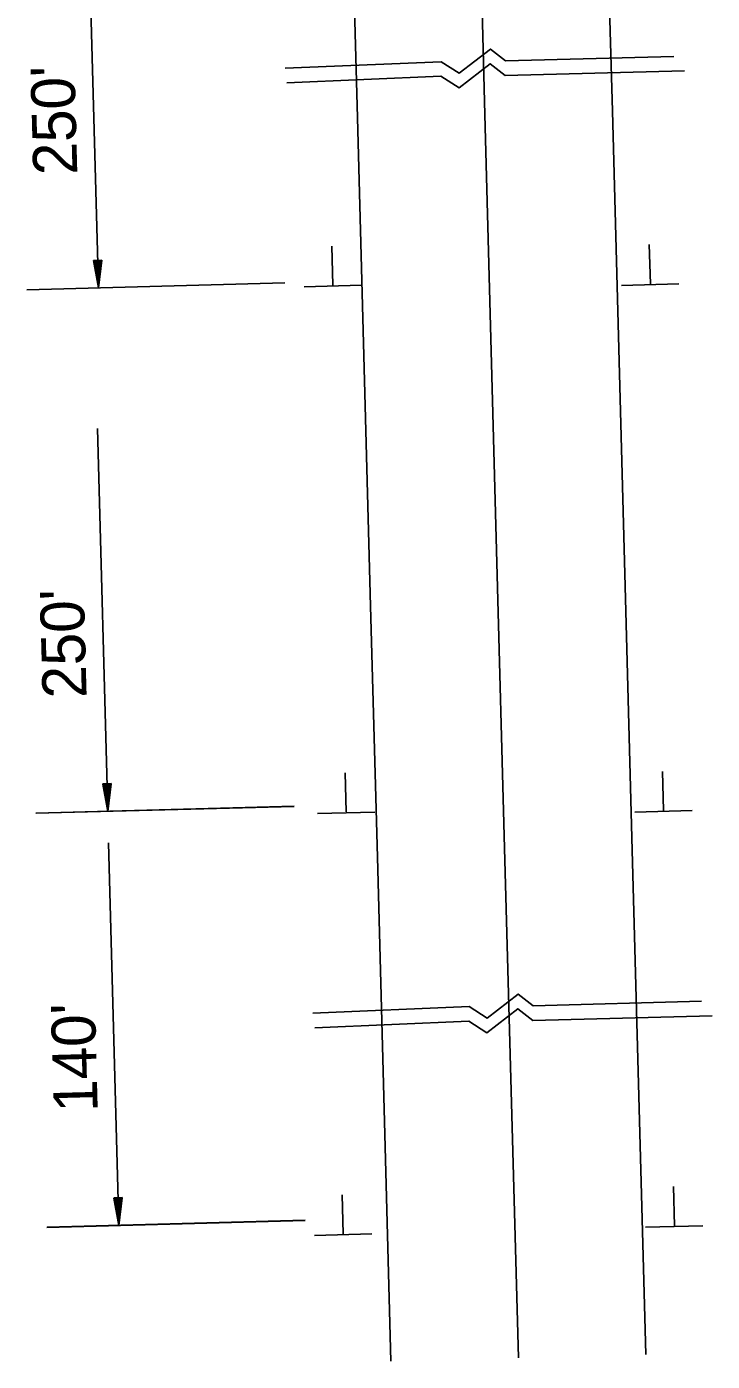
# Model space of a CAD drawing. Extents: x 1926836 to 1933254, y 596317 to 604524.
# Drawn here: x 1930895.5 to 1930991.2, y 598192.1 to 598378.3 of the extents above; entities that cross this region are included whole.
import ezdxf

# ---------------------------------------------------------------- set-up
doc = ezdxf.new("R2010")
doc.units = 0
doc.layers.add('Default', color=7, linetype='Continuous')

msp = doc.modelspace()

# ---------------------------------------------------------------- linework, layer by layer
at = {"layer": 'Default'}
for p, q in [((1930941.69, 598365.58), (1930939.79, 598436.16)), ((1930959.47, 598366.06), (1930957.58, 598436.64)), ((1930977.25, 598366.53), (1930975.36, 598437.12)), ((1930905.56, 598341.88), (1930904.12, 598395.26)), ((1930943.52, 598297.44), (1930941.69, 598365.58)), ((1930961.15, 598303.48), (1930959.47, 598366.06)), ((1930979.08, 598298.45), (1930977.25, 598366.53)), ((1930938.27, 598342.24), (1930938.12, 598347.7)), ((1930982.55, 598342.44), (1930982.4, 598347.9)), ((1930906.03, 598345.73), (1930904.88, 598345.7)), ((1930904.88, 598345.7), (1930905.56, 598341.88)), ((1930904.97, 598345.7), (1930905.54, 598342.52)), ((1930905.07, 598345.7), (1930905.52, 598343.18)), ((1930905.17, 598345.71), (1930905.51, 598343.82)), ((1930905.27, 598345.71), (1930905.49, 598344.47)), ((1930905.36, 598345.71), (1930905.47, 598345.11)), ((1930905.54, 598345.72), (1930905.47, 598345.11)), ((1930905.64, 598345.72), (1930905.49, 598344.47)), ((1930905.74, 598345.72), (1930905.51, 598343.82)), ((1930905.84, 598345.72), (1930905.52, 598343.18)), ((1930905.93, 598345.73), (1930905.54, 598342.52)), ((1930906.03, 598345.73), (1930905.56, 598341.88)), ((1930895.54, 598341.61), (1930931.56, 598342.58)), ((1930942.25, 598342.23), (1930934.25, 598342.02)), ((1930986.53, 598342.43), (1930978.53, 598342.21)), ((1930906.86, 598268.84), (1930905.42, 598322.22)), ((1930962.22, 598263.66), (1930961.15, 598303.48)), ((1930980.02, 598263.41), (1930979.08, 598298.45)), ((1930944.46, 598262.4), (1930943.52, 598297.44)), ((1930940.12, 598268.72), (1930939.98, 598274.18)), ((1930984.4, 598268.92), (1930984.25, 598274.38)), ((1930907.31, 598272.65), (1930906.16, 598272.62)), ((1930906.16, 598272.62), (1930906.84, 598268.8)), ((1930907.33, 598272.69), (1930906.18, 598272.66)), ((1930906.18, 598272.66), (1930906.86, 598268.84)), ((1930906.25, 598272.63), (1930906.82, 598269.44)), ((1930906.27, 598272.66), (1930906.84, 598269.48)), ((1930906.35, 598272.63), (1930906.8, 598270.1)), ((1930906.37, 598272.67), (1930906.82, 598270.14)), ((1930906.45, 598272.63), (1930906.78, 598270.74)), ((1930906.47, 598272.67), (1930906.8, 598270.78)), ((1930906.55, 598272.63), (1930906.77, 598271.39)), ((1930906.56, 598272.67), (1930906.79, 598271.43)), ((1930906.64, 598272.64), (1930906.75, 598272.03)), ((1930906.66, 598272.67), (1930906.77, 598272.07)), ((1930906.82, 598272.64), (1930906.75, 598272.03)), ((1930906.84, 598272.68), (1930906.77, 598272.07)), ((1930906.92, 598272.64), (1930906.77, 598271.39)), ((1930907.02, 598272.65), (1930906.78, 598270.74)), ((1930906.94, 598272.68), (1930906.79, 598271.43)), ((1930907.04, 598272.68), (1930906.8, 598270.78)), ((1930907.12, 598272.65), (1930906.8, 598270.1)), ((1930907.13, 598272.69), (1930906.82, 598270.14)), ((1930907.21, 598272.65), (1930906.82, 598269.44)), ((1930907.23, 598272.69), (1930906.84, 598269.48)), ((1930907.31, 598272.65), (1930906.84, 598268.8)), ((1930907.33, 598272.69), (1930906.86, 598268.84)), ((1930896.82, 598268.53), (1930932.84, 598269.5)), ((1930896.84, 598268.57), (1930932.86, 598269.54)), ((1930944.11, 598268.71), (1930936.1, 598268.49)), ((1930988.38, 598268.9), (1930980.38, 598268.69)), ((1930908.41, 598211.05), (1930906.97, 598264.43)), ((1930946.35, 598192.05), (1930944.46, 598262.4)), ((1930964.13, 598192.53), (1930962.22, 598263.66)), ((1930981.91, 598193.01), (1930980.02, 598263.41)), ((1930985.91, 598210.98), (1930985.76, 598216.45)), ((1930908.86, 598214.86), (1930907.71, 598214.83)), ((1930907.71, 598214.83), (1930908.39, 598211.01)), ((1930908.88, 598214.9), (1930907.73, 598214.87)), ((1930907.73, 598214.87), (1930908.41, 598211.05)), ((1930907.81, 598214.83), (1930908.37, 598211.65)), ((1930907.82, 598214.87), (1930908.39, 598211.69)), ((1930907.9, 598214.84), (1930908.35, 598212.31)), ((1930907.92, 598214.88), (1930908.37, 598212.35)), ((1930908, 598214.84), (1930908.34, 598212.95)), ((1930908.02, 598214.88), (1930908.35, 598212.99)), ((1930908.1, 598214.84), (1930908.32, 598213.6)), ((1930908.12, 598214.88), (1930908.34, 598213.64)), ((1930908.2, 598214.84), (1930908.3, 598214.24)), ((1930908.21, 598214.88), (1930908.32, 598214.28)), ((1930908.38, 598214.85), (1930908.3, 598214.24)), ((1930908.39, 598214.89), (1930908.32, 598214.28)), ((1930908.47, 598214.85), (1930908.32, 598213.6)), ((1930908.49, 598214.89), (1930908.34, 598213.64)), ((1930908.57, 598214.85), (1930908.34, 598212.95)), ((1930908.59, 598214.89), (1930908.35, 598212.99)), ((1930908.67, 598214.86), (1930908.35, 598212.31)), ((1930908.69, 598214.9), (1930908.37, 598212.35)), ((1930908.76, 598214.86), (1930908.37, 598211.65)), ((1930908.78, 598214.9), (1930908.39, 598211.69)), ((1930908.86, 598214.86), (1930908.39, 598211.01)), ((1930908.88, 598214.9), (1930908.41, 598211.05)), ((1930939.69, 598209.84), (1930939.54, 598215.3)), ((1930898.37, 598210.74), (1930934.39, 598211.71)), ((1930898.39, 598210.78), (1930934.41, 598211.75)), ((1930989.89, 598210.97), (1930981.89, 598210.76)), ((1930943.67, 598209.83), (1930935.67, 598209.62))]:
    msp.add_line(p, q, dxfattribs=at)
for points in [[(1930931.59, 598372.52), (1930953.37, 598373.43), (1930955.89, 598371.84), (1930960.23, 598375.19), (1930962.32, 598373.54), (1930985.81, 598374.17)], [(1930931.84, 598370.48), (1930953.34, 598371.39), (1930955.86, 598369.79), (1930960.2, 598373.15), (1930962.29, 598371.5), (1930987.31, 598372.16)], [(1930935.47, 598240.63), (1930957.25, 598241.55), (1930959.77, 598239.95), (1930964.11, 598243.31), (1930966.2, 598241.66), (1930989.69, 598242.29)], [(1930935.72, 598238.6), (1930957.22, 598239.5), (1930959.74, 598237.91), (1930964.08, 598241.26), (1930966.17, 598239.61), (1930991.19, 598240.28)]]:
    msp.add_lwpolyline(points, dxfattribs=at)

# ---------------------------------------------------------------- texts
for s, p in [("250'", (1930902.61, 598357.69)), ("250'", (1930903.91, 598284.66)), ("140'", (1930905.46, 598226.87))]:
    msp.add_text(s, height=6.14, rotation=91.5377, dxfattribs=at).set_placement(p)

doc.saveas('drawing.dxf')
